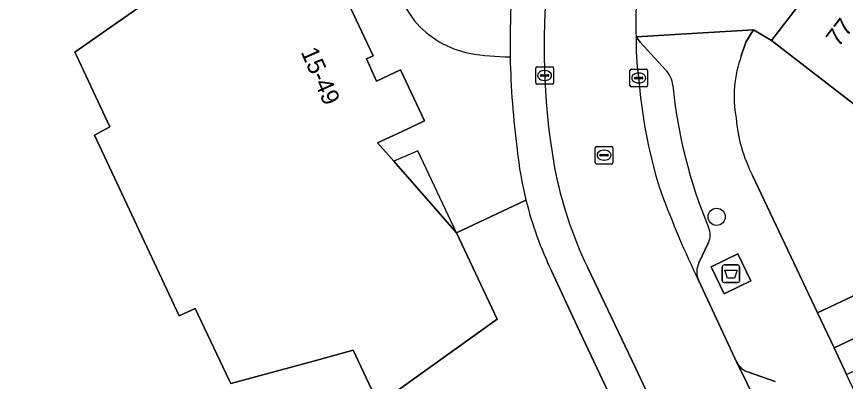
# Model space of a CAD drawing. Extents: x 159039 to 160102, y 381214 to 382524.
# Drawn here: x 159108.36 to 159155.58, y 381414.38 to 381435.17 of the extents above; entities that cross this region are included whole.
import ezdxf

# ---------------------------------------------------------------- set-up
doc = ezdxf.new("R2010")
doc.units = 0
for name, color, linetype in [('IMGEO_Afval_apart_plaats', 7, 'Continuous'), ('IMGEO_Boom', 7, 'Continuous'), ('IMGEO_Erf', 7, 'Continuous'), ('IMGEO_Groenvoorziening', 7, 'Continuous'), ('IMGEO_Kolk', 7, 'Continuous'), ('IMGEO_Pand', 7, 'Continuous'), ('IMGEO_Pand_nummerreeks', 7, 'Continuous'), ('IMGEO_Pand_overbouw', 7, 'Continuous'), ('IMGEO_Parkeervlak_open', 7, 'Continuous'), ('IMGEO_Rijbaan_lokaal_open', 7, 'Continuous'), ('IMGEO_Rioolput', 7, 'Continuous'), ('IMGEO_Voetpad_gesloten', 7, 'Continuous'), ('IMGEO_Voetpad_open', 7, 'Continuous')]:
    doc.layers.add(name, color=color, linetype=linetype)

msp = doc.modelspace()

# ---------------------------------------------------------------- linework, layer by layer
at = {"layer": 'IMGEO_Afval_apart_plaats'}
for p, q in [((159148.664, 381421.017), (159149.454, 381421.017)), ((159149.454, 381421.017), (159148.664, 381421.017)), ((159148.564, 381420.117), (159148.564, 381420.917)), ((159148.564, 381420.917), (159148.564, 381420.117)), ((159149.554, 381420.917), (159149.554, 381420.117)), ((159149.554, 381420.117), (159149.554, 381420.917)), ((159149.454, 381420.017), (159148.664, 381420.017)), ((159148.664, 381420.017), (159149.454, 381420.017))]:
    msp.add_line(p, q, dxfattribs=at)
msp.add_lwpolyline([(159148.707, 381420.731), (159149.411, 381420.731), (159149.262, 381420.261), (159148.856, 381420.261), (159148.707, 381420.731)], dxfattribs=at)
for centre, start, end in [((159148.664, 381420.917), 90, 180), ((159148.664, 381420.917), 90, 180), ((159149.454, 381420.917), 0, 90), ((159149.454, 381420.917), 360, 90), ((159148.664, 381420.117), 180, 270), ((159148.664, 381420.117), 180, 270), ((159149.454, 381420.117), 270, 0), ((159149.454, 381420.117), 270, 0)]:
    msp.add_arc(centre, 0.1, start, end, dxfattribs=at)
at = {"layer": 'IMGEO_Boom'}
msp.add_circle((159148.245, 381423.76), 0.489, dxfattribs=at)
at = {"layer": 'IMGEO_Erf'}
for points in [[(159150.293, 381426.116), (159153.986, 381418.297), (159164.713, 381423.363), (159162.622, 381424.971), (159165.502, 381428.715), (159167.593, 381427.107), (159168.391, 381428.145), (159169.317, 381429.348), (159167.226, 381430.956), (159167.879, 381431.805), (159169.077, 381433.435), (159169.569, 381434.075), (159172.101, 381437.365), (159174.226, 381435.729), (159175.127, 381436.901), (159176.18, 381438.27), (159174.055, 381439.906), (159176.546, 381443.144), (159178.951, 381446.271), (159181.077, 381444.635), (159181.982, 381445.811), (159179.856, 381447.447), (159183.312, 381451.939)], [(159156.467, 381429.881), (159151.367, 381433.804), (159150.342, 381434.421), (159149.911, 381433.719), (159149.648, 381432.939)]]:
    msp.add_lwpolyline(points, dxfattribs=at)
for centre, radius, start, end in [((159156.186, 381430.597), 6.945, 160.2962, 190.0538), ((159157.906, 381430.088), 8.586, 184.6945, 207.5525)]:
    msp.add_arc(centre, radius, start, end, dxfattribs=at)
at = {"layer": 'IMGEO_Groenvoorziening'}
for points in [[(159137.377, 381424.716), (159133.423, 381422.847), (159135.746, 381417.932), (159128.972, 381413.096), (159128.876, 381413.3), (159127.531, 381416.163), (159125.267, 381415.544), (159120.568, 381414.26), (159120.472, 381414.461), (159118.528, 381418.537), (159117.628, 381418.116), (159112.804, 381428.423), (159113.676, 381428.891), (159111.765, 381432.953), (159111.674, 381433.146), (159115.696, 381435.961), (159117.571, 381437.274), (159116.228, 381440.179), (159116.153, 381440.341), (159117.481, 381440.703), (159119.741, 381446.384), (159113.121, 381450.426), (159110.026, 381442.646), (159101.964, 381422.383)], [(159146.089, 381405.269), (159140.29, 381417.535), (159138.838, 381420.676)]]:
    msp.add_lwpolyline(points, dxfattribs=at)
msp.add_lwpolyline([(159164.247, 381418.838), (159165.805, 381419.572), (159167.281, 381420.261), (159166.567, 381421.792), (159154.931, 381416.296), (159155.647, 381414.78), (159159.724, 381416.706)], close=True, dxfattribs=at)
for centre, radius, start, end in [((159136.155, 381438.917), 6.495, 176.6826, 217.8127), ((159181.115, 381433.666), 44.643, 176.8399, 181.0063), ((159135.209, 381438.445), 5.462, 219.9876, 259.0272), ((159136.44, 381445.808), 12.926, 259.881, 270.1731), ((159157.965, 381429.877), 21.225, 194.0732, 205.6902)]:
    msp.add_arc(centre, radius, start, end, dxfattribs=at)
at = {"layer": 'IMGEO_Kolk'}
for p, q in [((159137.941, 381431.387), (159137.941, 381432.239)), ((159138.016, 381432.313), (159138.868, 381432.313)), ((159138.243, 381431.856), (159138.641, 381431.856)), ((159138.429, 381432.093), (159138.454, 381432.093)), ((159138.942, 381432.239), (159138.942, 381431.387)), ((159143.304, 381431.247), (159143.304, 381432.099)), ((159143.379, 381432.173), (159144.231, 381432.173)), ((159143.792, 381431.953), (159143.817, 381431.953)), ((159144.305, 381432.099), (159144.305, 381431.247)), ((159138.2, 381431.807), (159138.2, 381431.819)), ((159138.638, 381431.77), (159138.24, 381431.77)), ((159138.452, 381431.533), (159138.427, 381431.533)), ((159138.684, 381431.819), (159138.684, 381431.807)), ((159143.563, 381431.667), (159143.563, 381431.679)), ((159144.001, 381431.63), (159143.603, 381431.63)), ((159143.606, 381431.716), (159144.004, 381431.716)), ((159143.815, 381431.393), (159143.79, 381431.393)), ((159144.047, 381431.679), (159144.047, 381431.667)), ((159138.868, 381431.313), (159138.016, 381431.313)), ((159144.231, 381431.173), (159143.379, 381431.173))]:
    msp.add_line(p, q, dxfattribs=at)
for points in [[(159137.941, 381431.387), (159137.941, 381432.239)], [(159138.016, 381432.313), (159138.868, 381432.313)], [(159138.942, 381432.239), (159138.942, 381431.387)], [(159143.304, 381431.247), (159143.304, 381432.099)], [(159143.379, 381432.173), (159144.231, 381432.173)], [(159144.305, 381432.099), (159144.305, 381431.247)], [(159138.868, 381431.313), (159138.016, 381431.313)], [(159144.231, 381431.173), (159143.379, 381431.173)]]:
    msp.add_lwpolyline(points, dxfattribs=at)
for centre, radius, start, end in [((159138.018, 381432.237), 0.0765, 91.552, 178.448), ((159138.018, 381432.237), 0.0765, 91.552, 178.448), ((159138.24, 381431.816), 0.0403, 85.8775, 175.7526), ((159138.645, 381431.818), 0.0386, 1.7309, 96.639), ((159138.866, 381432.237), 0.0765, 1.552, 88.448), ((159138.866, 381432.237), 0.0765, 1.552, 88.448), ((159143.381, 381432.097), 0.0765, 91.552, 178.448), ((159143.381, 381432.097), 0.0765, 91.552, 178.448), ((159144.229, 381432.097), 0.0765, 1.552, 88.448), ((159144.229, 381432.097), 0.0765, 1.552, 88.448), ((159138.018, 381431.389), 0.0765, 181.552, 268.448), ((159138.018, 381431.389), 0.0765, 181.552, 268.448), ((159138.237, 381431.806), 0.0366, 178.938, 274.7102), ((159138.641, 381431.813), 0.043, 264.8664, 352.4533), ((159138.866, 381431.389), 0.0765, 271.552, 358.448), ((159138.866, 381431.389), 0.0765, 271.552, 358.448), ((159143.603, 381431.676), 0.0403, 85.8775, 175.7526), ((159143.6, 381431.666), 0.0366, 178.938, 274.7102), ((159144.004, 381431.673), 0.043, 264.8664, 352.4533), ((159144.008, 381431.678), 0.0386, 1.7309, 96.639), ((159143.381, 381431.249), 0.0765, 181.552, 268.448), ((159143.381, 381431.249), 0.0765, 181.552, 268.448), ((159144.229, 381431.249), 0.0765, 271.552, 358.448), ((159144.229, 381431.249), 0.0765, 271.552, 358.448)]:
    msp.add_arc(centre, radius, start, end, dxfattribs=at)
for centre, major_axis, ratio, start_param, end_param in [((159138.428, 381431.813), (-0.387, 0.002), 0.722429, 4.712389, 7.853982), ((159138.453, 381431.813), (-0.39, 0.002), 0.717154, 1.570796, 4.712389), ((159143.791, 381431.673), (-0.387, 0.002), 0.722429, 4.712389, 7.853982), ((159143.816, 381431.673), (-0.39, 0.002), 0.717154, 1.570796, 4.712389)]:
    msp.add_ellipse(centre, major_axis=major_axis, ratio=ratio, start_param=start_param, end_param=end_param, dxfattribs=at)
at = {"layer": 'IMGEO_Pand'}
for points in [[(159128.972, 381413.096), (159135.746, 381417.932), (159133.423, 381422.847), (159129.843, 381426.93), (159128.927, 381427.975), (159130.324, 381428.631), (159131.607, 381429.233), (159130.234, 381432.14), (159128.859, 381431.483), (159128.293, 381432.762), (159128.667, 381432.929), (159124.157, 381442.52)], [(159115.696, 381435.961), (159111.674, 381433.146), (159111.765, 381432.953), (159113.676, 381428.891), (159112.804, 381428.423), (159117.628, 381418.116), (159118.528, 381418.537), (159120.472, 381414.461), (159120.568, 381414.26), (159125.267, 381415.544), (159127.531, 381416.163), (159128.876, 381413.3)]]:
    msp.add_lwpolyline(points, dxfattribs=at)
msp.add_lwpolyline([(159159.969, 381434.434), (159154.87, 381438.357), (159151.367, 381433.804), (159156.467, 381429.881)], close=True, dxfattribs=at)
at = {"layer": 'IMGEO_Pand_overbouw'}
msp.add_lwpolyline([(159129.843, 381426.93), (159133.423, 381422.847), (159131.227, 381427.516), (159130.92, 381427.386)], close=True, dxfattribs=at)
at = {"layer": 'IMGEO_Parkeervlak_open'}
for points in [[(159145.352, 381432.126), (159143.88, 381433.706), (159143.66, 381434.008)], [(159147.231, 381421.142), (159147.78, 381422.299)], [(159147.072, 381420.421), (159147.21, 381420.154)], [(159149.4, 381415.463), (159151.164, 381411.865), (159152.42, 381409.329), (159163.115, 381386.6), (159166.148, 381380.052), (159173.158, 381365.109), (159175.314, 381360.345), (159181.799, 381346.618), (159183.007, 381344.058), (159183.216, 381343.614), (159183.92, 381342.134)], [(159151.577, 381414.383), (159149.996, 381414.926)]]:
    msp.add_lwpolyline(points, dxfattribs=at)
for centre, radius, start, end in [((159156.027, 381433.626), 12.373, 178.2289, 188.7473), ((159144.248, 381431.101), 1.507, 5.7662, 42.8746), ((159173.368, 381434), 29.656, 184.362, 196.7274), ((159173.941, 381434.026), 28.33, 185.6196, 202.5561), ((159199.526, 381445.276), 58.044, 199.95806, 205.35426), ((159146.874, 381422.727), 1.002, 334.7092, 25.5573), ((159148.313, 381420.625), 1.199, 154.4515, 203.1132), ((159150.38, 381415.951), 1.095, 206.4924, 249.4695)]:
    msp.add_arc(centre, radius, start, end, dxfattribs=at)
at = {"layer": 'IMGEO_Rijbaan_lokaal_open'}
msp.add_lwpolyline([(159140.88, 381420.897), (159143.611, 381415.16), (159146.252, 381409.527), (159151.164, 381411.865), (159149.4, 381415.463), (159147.21, 381420.154), (159147.072, 381420.421)], dxfattribs=at)
for centre, radius, start, end in [((159178.566, 381433.459), 40.156, 175.4766, 189.8928), ((159156.003, 381434.821), 12.37, 173.4089, 183.7692), ((159156.027, 381433.626), 12.373, 178.2289, 188.7473), ((159173.368, 381434), 29.656, 184.362, 196.7274), ((159161.704, 381430.926), 23.113, 190.8877, 205.7149), ((159199.526, 381445.276), 58.044, 199.95806, 205.35426)]:
    msp.add_arc(centre, radius, start, end, dxfattribs=at)
at = {"layer": 'IMGEO_Rioolput'}
for p, q in [((159141.329, 381426.845), (159141.329, 381427.697)), ((159141.404, 381427.771), (159142.256, 381427.771)), ((159142.33, 381427.697), (159142.33, 381426.845)), ((159141.588, 381427.265), (159141.588, 381427.277)), ((159142.026, 381427.228), (159141.628, 381427.228)), ((159141.631, 381427.314), (159142.029, 381427.314)), ((159141.817, 381427.551), (159141.842, 381427.551)), ((159142.072, 381427.277), (159142.072, 381427.265)), ((159142.256, 381426.771), (159141.404, 381426.771)), ((159141.84, 381426.991), (159141.815, 381426.991))]:
    msp.add_line(p, q, dxfattribs=at)
for points in [[(159141.329, 381426.845), (159141.329, 381427.697)], [(159141.404, 381427.771), (159142.256, 381427.771)], [(159142.33, 381427.697), (159142.33, 381426.845)], [(159142.256, 381426.771), (159141.404, 381426.771)]]:
    msp.add_lwpolyline(points, dxfattribs=at)
for centre, radius, start, end in [((159141.406, 381427.695), 0.0765, 91.552, 178.448), ((159141.406, 381427.695), 0.0765, 91.552, 178.448), ((159142.254, 381427.695), 0.0765, 1.552, 88.448), ((159142.254, 381427.695), 0.0765, 1.552, 88.448), ((159141.628, 381427.274), 0.0403, 85.8775, 175.7526), ((159141.625, 381427.264), 0.0366, 178.938, 274.7102), ((159142.029, 381427.271), 0.043, 264.8664, 352.4533), ((159142.033, 381427.276), 0.0386, 1.7309, 96.639), ((159141.406, 381426.847), 0.0765, 181.552, 268.448), ((159141.406, 381426.847), 0.0765, 181.552, 268.448), ((159142.254, 381426.847), 0.0765, 271.552, 358.448), ((159142.254, 381426.847), 0.0765, 271.552, 358.448)]:
    msp.add_arc(centre, radius, start, end, dxfattribs=at)
for centre, major_axis, ratio, start_param, end_param in [((159141.816, 381427.271), (-0.387, 0.002), 0.722429, 4.712389, 7.853982), ((159141.841, 381427.271), (-0.39, 0.002), 0.717154, 1.570796, 4.712389)]:
    msp.add_ellipse(centre, major_axis=major_axis, ratio=ratio, start_param=start_param, end_param=end_param, dxfattribs=at)
at = {"layer": 'IMGEO_Voetpad_gesloten'}
msp.add_lwpolyline([(159149.454, 381421.652), (159147.926, 381420.914), (159148.665, 381419.383), (159150.193, 381420.121)], close=True, dxfattribs=at)
at = {"layer": 'IMGEO_Voetpad_open'}
for points in [[(159129.671, 381439.293), (159129.781, 381440.254), (159119.741, 381446.384), (159117.481, 381440.703), (159124.157, 381442.52), (159128.667, 381432.929), (159128.293, 381432.762), (159128.859, 381431.483), (159130.234, 381432.14), (159131.607, 381429.233), (159130.324, 381428.631), (159128.927, 381427.975), (159129.843, 381426.93), (159133.423, 381422.847), (159137.377, 381424.716)], [(159143.66, 381434.008), (159150.342, 381434.421), (159151.367, 381433.804), (159154.87, 381438.357), (159154.961, 381438.476), (159155.303, 381438.92), (159151.05, 381442.244)], [(159149.648, 381432.939), (159149.911, 381433.719), (159150.342, 381434.421), (159143.66, 381434.008), (159143.88, 381433.706), (159145.352, 381432.126)], [(159194.413, 381332.419), (159187.998, 381346.282), (159187.65, 381347.019), (159186.898, 381348.612), (159155.647, 381414.78), (159154.931, 381416.296), (159153.986, 381418.297), (159150.293, 381426.116)], [(159164.713, 381423.363), (159153.986, 381418.297), (159154.931, 381416.296), (159166.567, 381421.792)], [(159147.78, 381422.299), (159147.231, 381421.142)], [(159138.838, 381420.676), (159140.29, 381417.535), (159146.089, 381405.269), (159166.925, 381361.075), (159176.573, 381340.671), (159177.417, 381338.702), (159179.725, 381332.403), (159181.079, 381328.582), (159182.155, 381325.087), (159183.485, 381320.552), (159183.58, 381320.071), (159185.351, 381312.004), (159185.783, 381309.99), (159186.535, 381306.759), (159187.645, 381285.734), (159188.179, 381280.338)], [(159183.211, 381330.948), (159181.577, 381334.596), (159179.38, 381339.291), (159178.484, 381341.207), (159178.201, 381341.808), (159168.866, 381361.603), (159147.869, 381406.077), (159147.453, 381406.965), (159146.252, 381409.527), (159143.611, 381415.16), (159140.88, 381420.897)], [(159147.21, 381420.154), (159149.4, 381415.463)], [(159149.996, 381414.926), (159151.577, 381414.383)]]:
    msp.add_lwpolyline(points, dxfattribs=at)
msp.add_lwpolyline([(159148.665, 381419.383), (159147.926, 381420.914), (159149.454, 381421.652), (159150.193, 381420.121)], close=True, dxfattribs=at)
for centre, radius, start, end in [((159136.155, 381438.917), 6.495, 176.6826, 217.8127), ((159178.566, 381433.459), 40.156, 175.4766, 189.8928), ((159181.115, 381433.666), 44.643, 176.8399, 181.0063), ((159156.003, 381434.821), 12.37, 173.4089, 183.7692), ((159135.209, 381438.445), 5.462, 219.9876, 259.0272), ((159136.44, 381445.808), 12.926, 259.881, 270.1731), ((159181.766, 381433.668), 45.293, 180.9942, 187.7322), ((159181.766, 381433.668), 45.293, 180.9942, 187.7322), ((159156.186, 381430.597), 6.945, 160.2962, 190.0538), ((159144.248, 381431.101), 1.507, 5.7662, 42.8746), ((159173.941, 381434.026), 28.33, 185.6196, 202.5561), ((159157.906, 381430.088), 8.586, 184.6945, 207.5525), ((159156.202, 381429.435), 19.407, 185.502, 194.0722), ((159156.202, 381429.435), 19.407, 185.502, 194.0722), ((159161.704, 381430.926), 23.113, 190.8877, 205.7149), ((159157.965, 381429.877), 21.225, 194.0732, 205.6902), ((159146.874, 381422.727), 1.002, 334.7092, 25.5573), ((159148.313, 381420.625), 1.199, 154.4515, 203.1132), ((159150.38, 381415.951), 1.095, 206.4924, 249.4695)]:
    msp.add_arc(centre, radius, start, end, dxfattribs=at)

# ---------------------------------------------------------------- texts
at = {"layer": 'IMGEO_Pand_nummerreeks'}
for s, rotation, p in [('77', 52.4305, (159155.186, 381433.389)), ('15-49', 293.871, (159124.53, 381433.159))]:
    msp.add_text(s, height=1, rotation=rotation, dxfattribs=at).set_placement(p)

doc.saveas('drawing.dxf')
